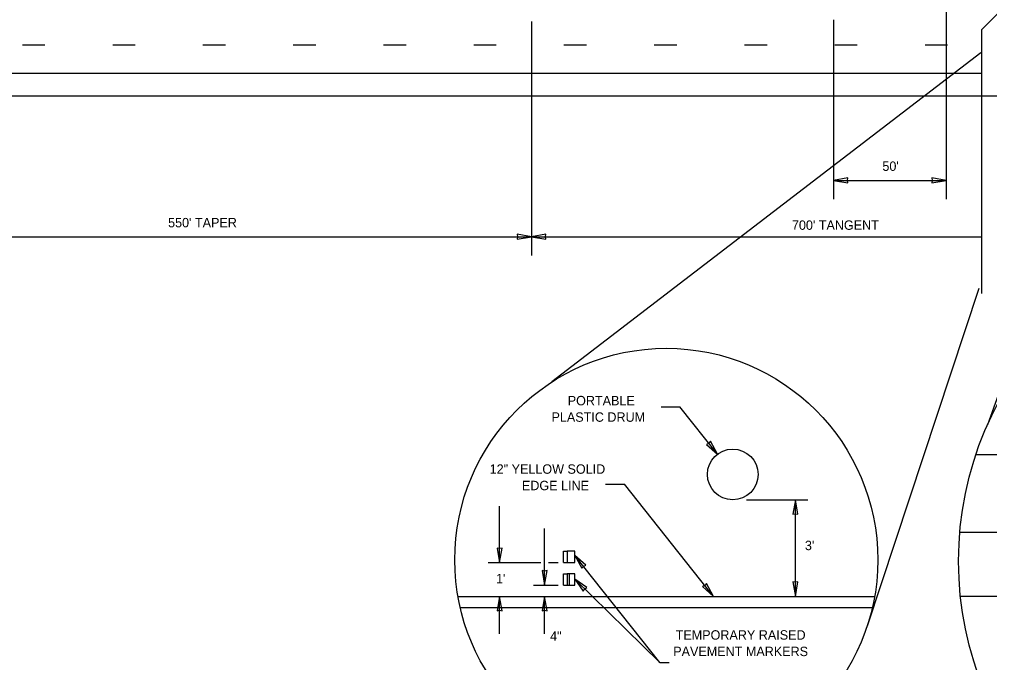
# Model space of a CAD drawing. Extents: x -2541 to -1265, y -5743 to -4928.
# Drawn here: x -2108.9 to -1696.1, y -5458.9 to -5185.3 of the extents above; entities that cross this region are included whole.
import ezdxf

# ---------------------------------------------------------------- set-up
doc = ezdxf.new("R2010")
doc.units = 0
for name, color, linetype in [('Level 42', 7, 'Continuous'), ('Level 45', 7, 'Continuous'), ('Level 46', 7, 'Continuous'), ('Level 49', 7, 'Continuous'), ('Level 50', 7, 'Continuous'), ('TR_WZ_TC_Edge Lines', 7, 'Continuous')]:
    doc.layers.add(name, color=color, linetype=linetype)

msp = doc.modelspace()

# ---------------------------------------------------------------- linework, layer by layer
at = {"layer": 'Level 45'}
for p, q in [((-1877.39, -5416.29), (-1877.39, -5411.49)), ((-1877.39, -5411.49), (-1875.79, -5411.49)), ((-1872.59, -5411.49), (-1875.79, -5411.49)), ((-1875.79, -5411.49), (-1875.79, -5416.29)), ((-1872.59, -5416.29), (-1872.59, -5411.49)), ((-1877.39, -5416.29), (-1875.79, -5416.29)), ((-1875.79, -5416.29), (-1872.59, -5416.29)), ((-1877.39, -5425.89), (-1877.39, -5421.09)), ((-1877.39, -5421.09), (-1875.79, -5421.09)), ((-1872.59, -5421.09), (-1875.79, -5421.09)), ((-1875.79, -5421.09), (-1875.79, -5425.89)), ((-1874.83, -5421.09), (-1875.79, -5421.09)), ((-1875.79, -5421.09), (-1875.79, -5425.89)), ((-1872.59, -5425.89), (-1872.59, -5421.09)), ((-1877.39, -5425.89), (-1875.79, -5425.89)), ((-1875.79, -5425.89), (-1872.59, -5425.89)), ((-1875.79, -5425.89), (-1874.83, -5425.89)), ((-1922.32, -5430.69), (-1745.01, -5430.69)), ((-1708.54, -5430.68), (-1424.11, -5430.68)), ((-1921.35, -5435.49), (-1745.98, -5435.49))]:
    msp.add_line(p, q, dxfattribs=at)
msp.add_lwpolyline([(-1874.83, -5425.89), (-1874.83, -5421.09)], dxfattribs=at)
at = {"layer": 'Level 46'}
for p, q in [((-1714.59, -5182.24), (-1714.59, -5261.76)), ((-1891, -5186.16), (-1891, -5285.76)), ((-1762.59, -5185.46), (-1762.59, -5261.76)), ((-2107.6, -5196.16), (-2098, -5196.16)), ((-2069.2, -5196.16), (-2059.6, -5196.16)), ((-2030.8, -5196.16), (-2021.2, -5196.16)), ((-1992.4, -5196.16), (-1982.8, -5196.16)), ((-1954, -5196.16), (-1944.4, -5196.16)), ((-1915.6, -5196.16), (-1906, -5196.16)), ((-1877.2, -5196.16), (-1867.6, -5196.16)), ((-1838.8, -5196.16), (-1829.2, -5196.16)), ((-1800.4, -5196.16), (-1790.8, -5196.16)), ((-1762, -5196.16), (-1752.4, -5196.16)), ((-1723.6, -5196.16), (-1714, -5196.16)), ((-1699.86, -5199.54), (-1882.3, -5339.46)), ((-2451.65, -5208.16), (-1699.44, -5208.16)), ((-2451.65, -5217.76), (-1737.89, -5217.76)), ((-1737.89, -5217.76), (-1460.65, -5217.76)), ((-1762.59, -5253.76), (-1714.59, -5253.76)), ((-2411.57, -5277.76), (-1865.75, -5277.76)), ((-1865.75, -5277.76), (-1699.44, -5277.76)), ((-1669.29, -5280.24), (-1697.04, -5357.77)), ((-1700.73, -5299.7), (-1748.21, -5443.42)), ((-1835.87, -5350.07), (-1827.87, -5350.07)), ((-1811.88, -5370.21), (-1827.87, -5350.07)), ((-1859.51, -5382.91), (-1851.51, -5382.91)), ((-1813.56, -5430.69), (-1851.51, -5382.91)), ((-1799.6, -5389.64), (-1773.38, -5389.64)), ((-1778.74, -5430.69), (-1778.74, -5389.64)), ((-1904.59, -5416.29), (-1904.59, -5392.29)), ((-1885.44, -5425.89), (-1885.44, -5401.89)), ((-1836.39, -5458.84), (-1872.59, -5413.26)), ((-1909.39, -5416.29), (-1887.04, -5416.29)), ((-1883.84, -5416.29), (-1879.63, -5416.29)), ((-1836.39, -5458.84), (-1872.59, -5423.36)), ((-1890.19, -5425.89), (-1879.63, -5425.89)), ((-1904.59, -5446.69), (-1904.59, -5430.69)), ((-1885.44, -5446.69), (-1885.44, -5430.69)), ((-1836.39, -5458.84), (-1832.39, -5458.84))]:
    msp.add_line(p, q, dxfattribs=at)
for centre, radius in [((-1566.32, -5415.75), 143), ((-1833.67, -5415.19), 90)]:
    msp.add_circle(centre, radius, dxfattribs=at)
at = {"layer": 'Level 49'}
for p, q in [((-1756.45, -5252.67), (-1762.59, -5253.76)), ((-1762.59, -5253.76), (-1756.45, -5254.84)), ((-1756.64, -5253.76), (-1756.45, -5252.67)), ((-1756.45, -5254.84), (-1756.64, -5253.76)), ((-1714.59, -5253.76), (-1720.74, -5252.67)), ((-1720.74, -5252.67), (-1720.55, -5253.76)), ((-1720.55, -5253.76), (-1720.74, -5254.84)), ((-1720.74, -5254.84), (-1714.59, -5253.76)), ((-1891, -5277.76), (-1897.15, -5276.67)), ((-1897.15, -5276.67), (-1896.96, -5277.76)), ((-1896.96, -5277.76), (-1897.15, -5278.84)), ((-1897.15, -5278.84), (-1891, -5277.76)), ((-1884.86, -5276.67), (-1891, -5277.76)), ((-1891, -5277.76), (-1884.86, -5278.84)), ((-1885.05, -5277.76), (-1884.86, -5276.67)), ((-1884.86, -5278.84), (-1885.05, -5277.76)), ((-1815.58, -5365.55), (-1816.55, -5366.07)), ((-1814.85, -5364.72), (-1815.58, -5365.55)), ((-1811.88, -5370.21), (-1814.85, -5364.72)), ((-1816.55, -5366.07), (-1811.88, -5370.21)), ((-1778.74, -5389.64), (-1779.83, -5395.79)), ((-1777.66, -5395.79), (-1778.74, -5389.64)), ((-1779.83, -5395.79), (-1778.74, -5395.6)), ((-1778.74, -5395.6), (-1777.66, -5395.79)), ((-1904.59, -5410.33), (-1905.67, -5410.14)), ((-1905.67, -5410.14), (-1904.59, -5416.29)), ((-1904.59, -5416.29), (-1903.5, -5410.14)), ((-1903.5, -5410.14), (-1904.59, -5410.33)), ((-1867.92, -5417.4), (-1872.59, -5413.27)), ((-1872.59, -5413.27), (-1869.62, -5418.75)), ((-1869.62, -5418.75), (-1868.89, -5417.93)), ((-1868.89, -5417.93), (-1867.92, -5417.4)), ((-1885.44, -5419.93), (-1886.53, -5419.74)), ((-1886.53, -5419.74), (-1885.44, -5425.89)), ((-1885.44, -5425.89), (-1884.36, -5419.74)), ((-1884.36, -5419.74), (-1885.44, -5419.93)), ((-1867.44, -5426.89), (-1872.59, -5423.37)), ((-1872.59, -5423.37), (-1868.96, -5428.44)), ((-1868.96, -5428.44), (-1868.34, -5427.53)), ((-1868.34, -5427.53), (-1867.44, -5426.89)), ((-1817.27, -5426.03), (-1818.23, -5426.55)), ((-1818.23, -5426.55), (-1813.56, -5430.69)), ((-1816.54, -5425.2), (-1817.27, -5426.03)), ((-1813.56, -5430.69), (-1816.54, -5425.2)), ((-1778.74, -5424.73), (-1779.83, -5424.54)), ((-1779.83, -5424.54), (-1778.74, -5430.69)), ((-1778.74, -5430.69), (-1777.66, -5424.54)), ((-1777.66, -5424.54), (-1778.74, -5424.73)), ((-1904.59, -5430.69), (-1905.67, -5436.83)), ((-1903.5, -5436.83), (-1904.59, -5430.69)), ((-1885.44, -5430.69), (-1886.53, -5436.83)), ((-1884.36, -5436.83), (-1885.44, -5430.69)), ((-1905.67, -5436.83), (-1904.59, -5436.64)), ((-1904.59, -5436.64), (-1903.5, -5436.83)), ((-1886.53, -5436.83), (-1885.44, -5436.64)), ((-1885.44, -5436.64), (-1884.36, -5436.83))]:
    msp.add_line(p, q, dxfattribs=at)
at = {"layer": 'Level 50'}
for p, q in [((-1699.44, -5189.63), (-1690.08, -5180.27)), ((-1699.44, -5301.83), (-1699.44, -5189.63))]:
    msp.add_line(p, q, dxfattribs=at)
msp.add_circle((-1805.38, -5378.84), 10.8, dxfattribs=at)
at = {"layer": 'TR_WZ_TC_Edge Lines'}
for p, q in [((-1701.94, -5370.4), (-1430.7, -5370.4)), ((-1708.79, -5403.4), (-1424.11, -5403.4))]:
    msp.add_line(p, q, dxfattribs=at)

# ---------------------------------------------------------------- texts
at = {"layer": 'Level 42'}
for s, p in [("50'", (-1741.73, -5249.73)), ("550' TAPER", (-2045.62, -5273.74)), ("700' TANGENT", (-1780.22, -5274.8)), ('PORTABLE', (-1875.6, -5349.44)), ('PLASTIC DRUM', (-1882.5, -5356.44)), ('12" YELLOW SOLID', (-1908.81, -5378.55)), ('EDGE LINE', (-1895.08, -5385.55)), ("3'", (-1774.69, -5411.04)), ("1'", (-1906.1, -5425.13)), ('4"', (-1883.09, -5449.61)), ('TEMPORARY RAISED', (-1829.68, -5449.11)), ('PAVEMENT MARKERS', (-1830.72, -5456.11))]:
    msp.add_text(s, height=4, dxfattribs=at).set_placement(p)

doc.saveas('drawing.dxf')
